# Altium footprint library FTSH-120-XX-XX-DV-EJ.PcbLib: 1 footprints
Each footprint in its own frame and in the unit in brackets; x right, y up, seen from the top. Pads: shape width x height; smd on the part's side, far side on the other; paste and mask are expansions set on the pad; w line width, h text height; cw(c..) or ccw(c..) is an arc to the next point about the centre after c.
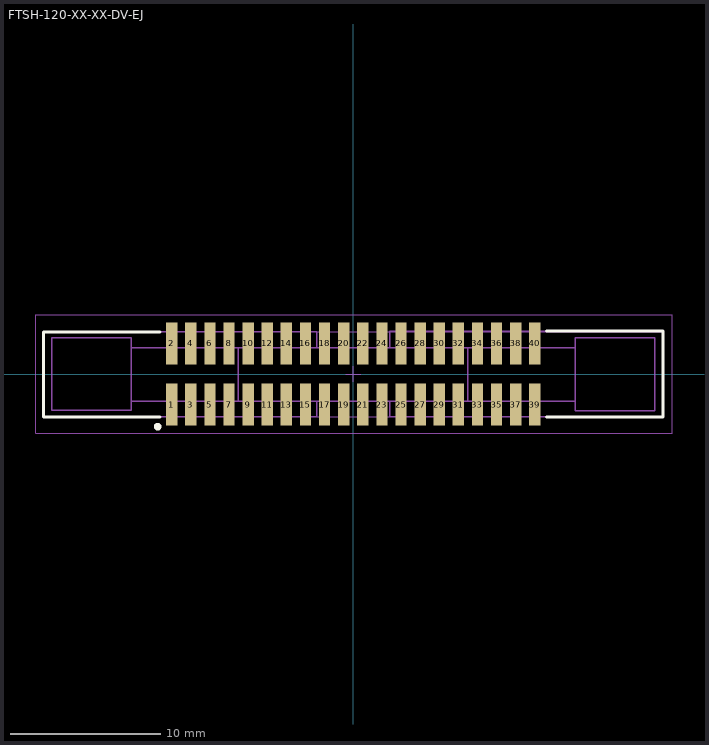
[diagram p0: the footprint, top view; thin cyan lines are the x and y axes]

## FTSH-120-XX-XX-DV-EJ [mm] "1.27mm pitch, 40 pin, terminal strip; vertical, double row, SMT"
height 5.97
pads (40):
  rect 0.75x2.8 smd mask+0: 1(-12.065,-2.032) 2(-12.065,2.032) 3(-10.795,-2.032) 4(-10.795,2.032) 5(-9.525,-2.032) 6(-9.525,2.032) 7(-8.255,-2.032) 8(-8.255,2.032) 9(-6.985,-2.032) 10(-6.985,2.032) 11(-5.715,-2.032) 12(-5.715,2.032) 13(-4.445,-2.032) 14(-4.445,2.032) 15(-3.175,-2.032) 16(-3.175,2.032) 17(-1.905,-2.032) 18(-1.905,2.032) 19(-0.635,-2.032) 20(-0.635,2.032) 21(0.635,-2.032) 22(0.635,2.032) 23(1.905,-2.032) 24(1.905,2.032) 25(3.175,-2.032) 26(3.175,2.032) 27(4.445,-2.032) 28(4.445,2.032) 29(5.715,-2.032) 30(5.715,2.032) 31(6.985,-2.032) 32(6.985,2.032) 33(8.255,-2.032) 34(8.255,2.032) 35(9.525,-2.032) 36(9.525,2.032) 37(10.795,-2.032) 38(10.795,2.032) 39(12.065,-2.032) 40(12.065,2.032)
Top Overlay:
  circle w0.25: c-13,-3.5 r0.125
  lines w0.2: -12.85,-2.85 -20.6,-2.85 -20.6,2.8 -12.85,2.8 ; 12.85,-2.85 20.6,-2.85 20.6,2.85 12.85,2.85
Mechanical 13:
  lines w0.1: -14.732,-1.8 -7.62,-1.8 ; -14.732,1.75 -7.62,1.75 ; -2.032,-1.778 -2.032,-2.794 -1.778,-2.794 -1.778,-1.778 ; -2.032,1.778 -2.032,2.794 -1.778,2.794 -1.778,1.778 ; -0.762,-1.778 -0.762,-2.794 -0.508,-2.794 -0.508,-1.778 ; -0.762,1.778 -0.762,2.794 -0.508,2.794 -0.508,1.778 ; 0.508,-1.778 0.508,-2.794 0.762,-2.794 0.762,-1.778 ; 0.508,1.778 0.508,2.794 0.762,2.794 0.762,1.778 ; 1.778,-1.778 1.778,-2.794 2.032,-2.794 2.032,-1.778 ; 1.778,1.778 1.778,2.794 2.032,2.794 2.032,1.778 ; 14.732,-1.8 7.62,-1.8 ; 14.732,1.75 7.62,1.75 ; -2.413,-1.8 -7.65,-1.8 -7.65,1.75 -2.413,1.75 ; -2.413,-1.8 -2.413,-2.85 -20.6,-2.85 -20.6,2.8 -2.413,2.8 -2.413,1.75 ; -2.413,-1.8 2.413,-1.8 ; -2.413,1.75 2.413,1.75 ; 2.413,-1.8 2.413,-2.85 20.6,-2.85 20.6,2.85 2.413,2.85 2.413,1.75 ; 2.413,-1.8 7.62,-1.8 ; 2.413,1.75 7.62,1.75 ; 7.62,-1.8 7.62,1.75 ; -20.05,-2.4 -14.75,-2.4 -14.75,2.4 -20.05,2.4 -20.05,-2.4 ; 14.75,-2.45 20.05,-2.45 20.05,2.4 14.75,2.4 14.75,-2.45
  text ".Designator" at 0.254,0.254 h1.52
Mechanical 15:
  lines w0.005: -20.6,-2.85 20.6,-2.85 20.6,2.8 -20.6,2.8 -20.6,-2.85
  lines w0.05: -0.5,0 0.5,0 ; 0,-0.5 0,0.5 ; -21.1,-3.95 21.2,-3.95 21.2,3.95 -21.1,3.95 -21.1,-3.95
